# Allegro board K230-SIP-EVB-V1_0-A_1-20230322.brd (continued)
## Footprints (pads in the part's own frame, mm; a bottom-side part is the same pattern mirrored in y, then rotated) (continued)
TC1206
  rect 1.397x1.651 smd: 1(-1.397,0) 2(1.397,0)
TP40
  round 1.016 smd: 1(0,0)
TYPE-C-USB16-20-126-H-SMD-B
  round 0.711 hole 0.711 unplated: (-2.89,2.6) (2.89,2.6)
  rect 0.305x1.448 smd: A1(-3.375,3.974) A4(-2.6,3.974) A5(-1.25,3.974) A6(-0.25,3.974) A7(0.25,3.974) A8(1.25,3.974) A9(2.6,3.974) A12(3.375,3.974) B1(3.075,3.974) B4(2.3,3.974) B5(1.75,3.974) B6(0.75,3.974) B7(-0.75,3.974) B8(-1.75,3.974) B9(-2.3,3.974) B12(-3.075,3.974)
  oval 1.143x2.159 hole 0.762x1.778: P1(-4.32,3.13) P2(4.32,3.13)
  oval 1.143x1.651 hole 0.762x1.27: P3(-4.32,-1.05) P4(4.32,-1.05)
unnamed
  round 5.08 hole 2.921: (-14,14) (-14,-14) (14,14) (14,-14)
  round 1.524 hole 1.524 unplated: (-10.5,10.5) (-10.5,-10.5) (10.5,10.5) (10.5,-10.5)
WSON8-065-0303-008-N
  rect 0.635x0.381 smd: 1(-1.41,0.975) 2(-1.41,0.325) 3(-1.41,-0.325) 4(-1.41,-0.975) 5(1.41,-0.975) 6(1.41,-0.325) 7(1.41,0.325) 8(1.41,0.975)
  rect 1.651x2.54 smd: 9(0,0)
X2-3215-008
  rect 1.016x1.778 smd: 1(-1.257,0) 2(1.257,0)
X4-2520-010
  rect 1.016x0.889 smd: 1(-0.914,-0.762) 2(0.914,-0.762) 3(0.914,0.762) 4(-0.914,0.762)
X4-3225-009
  rect 1.27x1.143 smd: 1(-1.1,-0.8) 2(1.1,-0.8) 3(1.1,0.8) 4(-1.1,0.8)

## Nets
AVDD0V8_MIPI: C130.1 C131.1 C199.1 C200.1 C201.1 FB22.2 TP18.1(TP) U19.M4(AVDD0P8_MIPI_0) U19.N5(AVDD0P8_MIPI_1)
AVDD0V8_PLL: C148.1 C150.1 C197.1 C198.1 FB25.2 TP20.1(TP) U19.D8(AVDD0P8_PLL)
AVDD1V8_MIPI: C110.1 C111.1 C202.1 C203.1 C204.1 FB18.2 R90.1 TP15.1(TP) U19.L4(AVDD1P8_MIPI_1) U19.M6(AVDD1P8_MIPI_0)
GND: C1.2 C2.2 C3.2 C4.2 C5.2 C6.2 C7.2 C8.2 C9.2 C10.2 C11.2 C12.1 C13.2 C14.2 C15.2 C16.2 C17.2 C18.2 C19.2 C20.2 C21.2 C22.2 C23.2 C24.2 C25.2 C26.1 C28.2 C29.2 C30.1 C31.2 C32.2 C35.1 C36.2 C37.2 C40.2 C41.2 C42.2 C43.2 C44.2 C45.2 C46.2 C47.2 C48.2 C49.2 C50.2 C51.2 C52.2 C53.1 C55.2 C56.2 C57.1 C58.2 C59.2 C60.1 C61.1 C62.2 C63.2 C64.1 C66.2 C67.2 C68.1 C69.2 C70.2 C71.2 C72.1 C73.2 C74.2 C75.2 C76.2 C77.1 C79.2 C80.2 C81.1 C82.2 C83.2 C84.1 C85.2 C86.2 C87.1 C88.2 C90.2 C91.2 C92.1 C93.2 C94.2 C95.2 C96.1 C97.2 C98.2 C99.2 C100.2 C101.2 C102.2 C103.2 C104.2 C105.2 C106.2 C107.2 C108.2 C109.2 C110.2 C111.2 C112.2 C113.2 C114.2 C115.2 C116.2 C117.2 C118.2 C119.2 C120.2 C121.2 C122.2 C123.2 C124.2 C125.2 C126.2 C127.2 C128.2 C129.2 C130.2 C131.2 C132.2 C133.2 C134.2 C135.2 C136.2 C137.2 C138.2 C139.2 C140.2 C141.1 C142.2 C143.2 C144.2 C145.2 C146.2 C147.2 C148.2 C149.2 C150.2 C151.2 C152.2 C153.2 C154.2 C155.2 C156.2 C157.2 C158.2 C159.2 C160.2 C161.2 C162.2 C163.2 C164.2 C165.2 C166.2 C167.2 C168.2 C169.2 C170.2 C171.2 C172.2 C173.2 C174.2 C175.2 C176.2 C177.2 C178.2 C179.2 C180.2 C181.2 C182.2 C183.2 C184.2 C185.2 C186.2 C187.2 C188.2 C189.2 C190.2 C191.2 C192.2 C193.2 C194.2 C195.2 C196.2 C197.2 C198.2 C199.2 C200.2 C201.2 C202.2 C203.2 C204.2 C205.2 C206.2 C207.2 C208.2 C209.2 C210.2 C211.2 C212.2 C213.2 C214.2 C215.2 C216.2 C217.2 C218.2 C219.2 C220.2 C221.2 C222.2 C223.2 C224.2 C225.2 C226.2 C227.2 C228.2 C229.2 C230.2 C231.2 C232.2 C233.2 C234.2 C235.2 C236.2 C237.2 C238.1 C239.2 C240.2 C241.2 C242.2 C243.2 C244.2 C245.2 C246.2 C247.2 C248.2 C249.2 C250.2 C251.2 C253.1 C254.2 C255.1 C258.2 C259.1 C271.2 C272.2 C273.1 C274.1 C278.1 C280.1 C282.2 C283.1 C284.1 C286.1 C288.2 C289.1 C290.1 C291.2 C292.1 C293.2 C294.1 C295.2 C296.2 C297.2 C298.2 C299.2 C301.2 C302.2 C303.2 C304.2 C305.2 C306.2 C308.1 C310.1 C311.2 C312.2 D2.1(ANODE) J1.A1(GND0) J1.A12(GND1) J1.B1(GND3) J1.B12(GND2) J1.P1 J1.P2 J1.P3 J1.P4 J3.1 J3.2 J4.1 J4.2 J7.2 J7.9 J7.10 J11.A1(GND0) J11.A12(GND1) J11.B1(GND3) J11.B12(GND2) J11.P1 J11.P2 J11.P3 J11.P4 J18.2 J21.5 J21.6 J21.11 J21.12 J21.17 J21.18 J21.23 J21.24 J21.28 J21.29 J21.33 J21.37 J21.54 J21.55 J22.1 J22.2 J22.7 J22.12 J22.15 J22.18 J22.21 J22.24 J22.27 J22.30 J22.31 J22.32 J27.A1(GND0) J27.A12(GND1) J27.B1(GND3) J27.B12(GND2) J27.P1 J27.P2 J27.P3 J27.P4 J30.17 J30.18 J30.27 J30.28 J31.6 J31.12 J32.5 J33.3 K1.1 K2.3 K2.4 K3.3 LED2.2(ANODE) M1.1 M2.1 M3.1 M4.1 M5.1 M6.1 Q2.2(SOURCE) Q4.2(SOURCE) R1.2 R2.2 R6.2 R9.2 R16.2 R17.2 R19.2 R24.2 R31.2 R38.1 R44.2 R48.1 R52.1 R55.2 R59.2 R65.2 R69.2 R72.2 R78.2 R82.2 R87.2 R91.2 R93.2 R98.2 R103.2 R104.2 R138.1 R139.1 R140.1 R163.2 R164.2 R170.1 R171.1 R193.2 R208.2 R267.2 TP22.1(TP) TP23.1(TP) TP24.1(TP) TP25.1(TP) TP26.1(TP) TP27.1(TP) TP28.1(TP) TP29.1(TP) TP30.1(TP) TP31.1(TP) TP32.1(TP) TP33.1(TP) TP34.1(TP) TP35.1(TP) TP36.1(TP) TP37.1(TP) TP38.1(TP) TP39.1(TP) TP40.1(TP) TP41.1(TP) TP42.1(TP) TP43.1(TP) TP44.1(TP) TP45.1(TP) TVS1.2(A2) TVS2.1(A1) TVS3.1(A1) TVS4.2(A2) TVS5.2(A2) TVS6.2(A2) TVS7.2(A2) TVS8.2(A2) TVS9.2(A2) TVS10.2(A2) TVS11.2(A2) TVS12.2(A2) TVS13.2(A2) TVS14.2(A2) TVS15.2(A2) U1.2(GND) U2.3(GND) U2.7(POWERPAD) U3.1(AGND) U3.2(PGND) U4.3(GND2) U4.4(GND1) U4.5(AGND) U4.17(EPAD) U5.1(AGND) U5.2(PGND) U6.4(PGND1) U6.8(SGND) U6.9(PGND2) U7.4(PGND1) U7.8(SGND) U7.9(PGND2) U8.4(PGND1) U8.8(SGND) U8.9(PGND2) U9.4(PGND1) U9.8(SGND) U9.9(PGND2) U10.3(GND) U10.7(POWERPAD) U11.3(GND) U11.7(POWERPAD) U12.3(GND) U12.7(POWERPAD) U13.3(GND) U13.7(POWERPAD) U14.3(GND) U14.7(POWERPAD) U15.6(GND) U15.11(TP) U16.8(GND1) U16.9(GND2) U17.3(GND) U17.7(POWERPAD) U18.3(GND) U18.7(POWERPAD) U19.B16(VSS1) U19.C4(VSS2) U19.C5(VSS3) U19.C8(VSS4) U19.D6(VSS7) U19.D7(VSS8) U19.D9(AVSS0) U19.D13(VSS9) U19.E4(AVSS1) U19.E5(AVSS2) U19.E11(VSS11) U19.E12(VSS12) U19.E15(VSS13) U19.E16(VSS14) U19.F3(VSS15) U19.F8(VSS16) U19.F10(VSS17) U19.F12(VSS18) U19.G3(VSS20) U19.G4(VSS21) U19.G8(VSS22) U19.G10(VSS23) U19.G12(VSS24) U19.G13(VSS25) U19.G14(VSS26) U19.G15(VSS19) U19.G16(VSS72) U19.H3(VSS27) U19.H5(VSS28) U19.H7(VSS29) U19.H9(VSS30) U19.H13(VSS31) U19.H15(VSS32) U19.J4(VSS33) U19.J5(VSS34) U19.J7(VSS35) U19.J9(VSS36) U19.J12(VSS37) U19.J13(VSS38) U19.J14(VSS39) U19.J15(VSS40) U19.K5(VSS41) U19.K7(VSS42) U19.K9(VSS43) U19.K12(VSS44) U19.K13(VSS45) U19.K14(VSS46) U19.K15(VSS47) U19.K16(VSS48) U19.L3(VSS49) U19.L5(VSS50) U19.L7(VSS51) U19.L9(VSS52) U19.L12(VSS53) U19.L15(VSS54) U19.M3(VSS0) U19.M5(VSS55) U19.M7(VSS56) U19.M9(VSS57) U19.M11(VSS58) U19.M12(VSS59) U19.N4(VSS60) U19.N6(VSS61) U19.N7(VSS62) U19.N9(VSS63) U19.N12(VSS64) U19.P7(VSS66) U19.P8(VSS67) U19.P9(VSS68) U19.P14(VSS69) U19.R1(VSS70) U19.T13(VSS71) U20.7(GND) U21.7(GND) U23.6(VSS) U23.10(GND1) U23.11(GND2) U23.12(GND3) U23.13(GND4) U24.1(GND) U25.1(GND) U26.1(GND) U27.2(GND) U29.1(GND) U30.7(GND) U30.9(GND1) U31.7(GND) U31.9(GND1) U32.4(GND) U33.3(GND1) U33.11(GND0) U34.1(GND) U35.7(GND) U36.3(GND) U36.7(POWERPAD) U37.4(GND) U38.1(GND) U39.1(GND) U40.1(GND) U41.6(VSS) U41.10(GND1) U41.11(GND2) U41.12(GND3) U41.13(GND4) Y1.2(GND) Y2.2(GND#2) Y2.4(GND#4) Y4.2(GND)
VBUS: F1.1 J1.A4(VBUS0) J1.A9(VBUS1) J1.B4(VBUS3) J1.B9(VBUS2)
VBUS_CHARGE: C8.1 J2.1 LED1.1(CATHODE) U1.4(VIN)
VBUS_IN: C1.1 C2.1 C3.1 C4.1 C5.1 C6.1 C7.1 C288.1 D1.2(K) D2.2(CATHODE) D3.2(K) J2.2 U33.4(VDD5)
VDD0V8_CPU: C47.1 C48.1 C58.1 C59.1 C175.1 C176.1 C177.1 C178.1 C179.1 C299.1 FB6.2 FB7.2 TP4.1(TP) U19.E10(VDD0P8_CPU_0) U19.F9(VDD0P8_CPU_1) U19.G9(VDD0P8_CPU_2)
VDD0V8_DDR_CORE: C123.1 C124.1 C211.1 C212.1 C213.1 C214.1 C215.1 FB21.2 TP17.1(TP) U19.H10(VDD0P8_DDR_CORE_0) U19.J10(VDD0P8_DDR_CORE_1) U19.K10(VDD0P8_DDR_CORE_2) U19.L10(VDD0P8_DDR_CORE_3)
VDD0V8_KPU: C18.1 C21.1 C31.1 C32.1 C180.1 C181.1 C182.1 C183.1 C184.1 C185.1 C186.1 C187.1 C188.1 C189.1 FB2.1 FB3.1 TP1.1(TP) U19.F5(VDD0P8_KPU_0) U19.F6(VDD0P8_KPU_1) U19.F7(VDD0P8_KPU_2) U19.G5(VDD0P8_KPU_3) U19.G6(VDD0P8_KPU_4) U19.G7(VDD0P8_KPU_5)
VDD1V1_DDR: C135.1 C136.1 C143.1 C144.1 C221.1 C222.1 C223.1 C224.1 C225.1 C231.1 C232.1 C233.1 C234.1 FB23.2 FB24.2 R94.2 TP19.1(TP) U19.F11(VDD1P1_DDR_IO_0) U19.F15(VDD1P1_DDR_VDD2_0) U19.G11(VDD1P1_DDR_IO_1) U19.J11(VDD1P1_DDR_IO_2) U19.K11(VDD1P1_DDR_IO_3) U19.L11(VDD1P1_DDR_IO_4) U19.M15(VDD1P1_DDR_VDD2_1)
VDD1V1_DDR_DRAM: C156.1 C157.1 C218.1 C219.1 C220.1 C306.1 FB26.2 TP21.1(TP) U19.F16(VDD1P1_DDR_VDDQ_0) U19.L16(VDD1P1_DDR_VDDQ_1)
VDD1V8_DDR_VDD1: C98.1 C100.1 C116.1 C117.1 C226.1 C227.1 C228.1 FB16.2 FB19.2 TP13.1(TP) U19.H14(VDD1P8_DDR_VDD1)
VDD_0V8: C82.1 C83.1 C159.1 C160.1 C161.1 C162.1 C163.1 C164.1 C165.1 C166.1 C167.1 C168.1 C169.1 C170.1 C171.1 C172.1 C173.1 C174.1 FB11.2 TP8.1(TP) U19.E6(VDD0P8_CORE_1) U19.E7(VDD0P8_CORE_2) U19.E9(VDD0P8_CORE_3) U19.H6(VDD0P8_CORE_4) U19.H8(VDD0P8_CORE_5) U19.J6(VDD0P8_CORE_6) U19.J8(VDD0P8_CORE_7) U19.K6(VDD0P8_CORE_8) U19.K8(VDD0P8_CORE_9) U19.L6(VDD0P8_CORE_10) U19.L8(VDD0P8_CORE_11) U19.M8(VDD0P8_CORE_12) U19.M10(VDD0P8_CORE_13)
VDD_1V1: C300.1 R95.1
VDD_1V8: C88.1 C121.1 C133.1 C139.1 C140.1 C147.1 C190.1 C191.1 C192.1 C247.1 C248.1 C249.1 C250.1 C251.1 C253.2 C254.1 C258.1 C291.1 C303.1 C304.1 FB12.2 J7.1 Q3.1(GATE) R47.1 R63.2 R73.2 R80.2 R89.1 R96.2 R99.2 R101.2 R122.1 R123.1 R124.1 R125.1 R126.1 R132.1 R136.1 R168.1 R179.1 R180.1 R181.1 R182.1 R183.1 R184.1 R185.1 R186.1 R195.1 R212.1 R222.1 TP9.1(TP) U13.6(IN) U15.1(IN1) U15.2(IN2) U16.4(IN) U17.6(IN) U19.D10(VDD1P8_1) U19.E8(VDD1P8_0) U19.F4(VDDIO3P3_3) U19.H4(VDDIO3P3_1) U19.K4(VDDIO3P3_4) U19.N10(VDDIO3P3_0) U19.N11(VDDIO3P3_5) U20.2(VCCA) U21.2(VCCA) U35.2(VCCA) U37.8(VCC) Y1.4(VCC)
VDD_1V8_ADC: C97.1 C193.1 C194.1 FB15.2 TP12.1(TP) U19.D5(AVDD1P8_ADC)
VDD_1V8_CODEC: C95.1 C195.1 C196.1 FB14.2 TP11.1(TP) U19.D4(AVDD1P8_CODEC)
VDD_1V8_USB: C94.1 C209.1 C210.1 FB13.2 TP10.1(TP) U19.C6(AVDD1P8_USB)
VDD_3V3: C73.1 C74.1 C99.1 C104.1 C112.1 C153.1 C205.1 C206.1 C271.1 C272.1 C311.1 C312.1 FB9.2 FB33.1 J21.57 J21.59 J22.5 J22.6 R37.1 R50.2 R53.2 R57.2 R84.2 R155.1 R194.2 R204.2 R220.1 R223.1 R224.2 R226.2 R265.1 R273.1 R274.1 R275.1 R276.1 R277.1 R278.1 R279.1 TP6.1(TP) TVS5.1(A1) TVS14.1(A1) U10.6(IN) U11.6(IN) U12.6(IN) U18.6(IN) U19.C9(VDD3P3_SD) U23.4(VDD) U41.4(VDD)
VDD_3V3_K210: FB10.2 J30.29 J30.30
VDD_3V3_USB: C70.1 C71.1 C207.1 C208.1 FB8.2 TP5.1(TP) U19.C7(AVDD3P3_USB)
VDD_5V: C9.1 C10.1 C11.1 C15.1 C16.1 C17.1 C24.1 C25.1 C26.2 C44.1 C45.1 C46.1 C51.1 C52.1 C53.2 C62.1 C63.1 C64.2 C75.1 C76.1 C77.2 C85.1 C86.1 C87.2 C137.1 C145.1 C273.2 C283.2 C284.2 C302.1 J2.3 J3.3 J3.4 J4.3 J4.4 J32.6 J33.1 Q5.2(SOURCE) R3.1 R5.1 R8.2 R14.1 R15.1 R23.2 R28.2 R30.1 R35.2 R42.1 R43.2 R49.2 R137.1 R162.1 R207.1 R264.1 R266.2 TP3.1(TP) U1.3(BAT) U2.6(IN) U3.3(VIN) U4.1(VIN3) U4.2(VIN1) U4.16(VIN2) U5.3(VIN) U6.3(IN) U7.3(IN) U8.3(IN) U9.3(IN) U15.4(BIAS) U16.1(BIAS) U27.5(IN) U30.6(VDD) U31.6(VDD) U36.6(IN)
VDD_5V_O: J21.56 J21.58 J21.60 J22.3 J22.4 Q5.3(DRAIN) R264.2
3D_CTRL_IN: J21.49 U19.P15(GPIO10)
3D_CTRL_OUT1: J21.47 U19.P16(GPIO11)
3D_CTRL_OUT2: J21.46 U19.P13(GPIO12)
ADC0: R229.1 U19.A7(ADC_0)
ADC1: R230.1 U19.A6(ADC_1)
ADC2: R178.2 U19.B6(ADC_2)
BOOT_CTL0: R99.1 SW1.1(A1) TVS3.2(A2) U19.C14(GPIO0)
BOOT_CTL1: R101.1 SW1.2(A2) TVS2.2(A2) U19.C15(GPIO1)
CC1: J1.A5(CC1) J1.B5(CC2) R1.1
CC_T: J27.A5(CC1) J27.B5(CC2) R193.1 TVS7.1(A1)
CLK24M_XIN: R97.2 R100.2 U19.A15(CLK24M_XIN)
CLK24M_XOUT: R105.2 U19.B15(CLK24M_XOUT)
CTRL0: J36.1 R170.2 U30.1(CTRL)
CTRL1: J36.2 R171.2 U31.1(CTRL)
DDR_VREF: C240.1 C241.1 C300.2 R95.2 R98.1 U19.H11(DDR_VREF)
DEBUG_DM: J27.A7(DN1) J27.B7(DN2) R188.1 U34.2(I/O_1)
DEBUG_DP: J27.A6(DP1) J27.B6(DP2) R187.1 U34.3(I/O_2)
EN: C115.1 C118.1 R57.1 R60.1 U12.4(EN)
EN_CORE_K210: J35.2 R64.1
EN_DDR_K210: J35.1 R86.1 R231.1
GPIO7: J34.3 U19.M16(GPIO7)
GPIO8: J34.8 U19.N16(GPIO8)
GPIO20: R213.1 U19.H2(GPIO20)
GPIO21: R214.1 U19.H1(GPIO21)
GPIO22: R215.1 U19.J1(GPIO22)
GPIO23: R216.1 U19.J2(GPIO23)
GPIO24: Q3.2(SOURCE) R222.2 U19.J3(GPIO24) U21.6(A4)
GPIO24_3V3: Q1.1(GATE) Q3.3(DRAIN) R135.2 R223.2
GPIO25: R127.1 R176.2
GPIO32: J38.1 R115.2 U21.12(B1)
GPIO32_1V8: R133.1 R177.2
GPIO33: J38.2 R116.2 U21.11(B2)
GPIO33_1V8: R134.1 R174.2
GPIO34: J34.1 J37.2 R118.2 U20.12(B1)
GPIO34_1V8: J21.32 R128.1
GPIO35: J32.1 J37.1 R119.2 U20.11(B2)
GPIO35_1V8: J21.34 R129.1
GPIO36: J37.3 R120.2 U20.10(B3)
GPIO36_1V8: J21.36 R130.1
GPIO37: J38.3 R121.2 U20.9(B4)
GPIO37_1V8: R131.1 R175.2
GPIO38: J34.9 U19.E3(GPIO38)
GPIO39: J34.14 U19.D1(GPIO39)
GPIO40: R110.1 U19.D2(GPIO40)
GPIO41: R111.1 U19.C1(GPIO41)
GPIO44: R112.1 U19.B1(GPIO44)
GPIO45: R113.1 U19.C2(GPIO45)
GPIO48: R218.1 U19.D3(GPIO48)
GPIO49: R219.1 U19.C3(GPIO49)
GPIO59: R173.2 U19.P4(GPIO59)
GPIO60: R114.1 U19.N3(GPIO60)
GPIO61: R117.1 U19.P3(GPIO61)
HP_INSERT_DET: J34.12 R169.1
HPOUTL: C281.1 C309.1 U19.B2(LINEOUTN)
HPOUTR: C279.1 C307.1 U19.A2(LINEOUTP(L))
HSYNC0: J21.51 J34.11 R229.2
IIC0_SCL: J21.38 R114.2 R179.2
IIC0_SDA: J21.40 R117.2 R180.2
IIC1_SCL: J21.43 R110.2 R181.2 R269.1
IIC1_SDA: J21.45 R111.2 R182.2 R268.1
IIC3_SCL: J21.41 R112.2 R183.2
IIC3_SDA: J21.39 R113.2 R184.2
IIC4_SCL: J22.8 J34.4 R185.2 R271.1
IIC4_SDA: J22.9 J34.6 R186.2 R270.1
INA226_0V8+: C78.2 C79.1 C80.1 C81.2 J30.2 L6.2 R40.1 R41.2
INA226_0V8-: FB11.1 J30.4 R40.2
INA226_1V8IO+: C89.2 C90.1 C91.1 C92.2 C93.1 J30.6 L7.2 R45.1 R46.2
INA226_1V8IO-: FB12.1 FB13.1 FB14.1 FB15.1 J30.8 R45.2
INA226_AVDDMIPI+: C128.1 C129.1 J30.9 R66.1 R68.1 U14.1(OUT)
INA226_AVDDMIPI-: FB22.1 J30.11 R66.2
INA226_CORE0+: C54.2 C55.1 C56.1 C57.2 L4.2 R25.1 R27.1 R29.2
INA226_CORE0-: FB7.1 R26.1 R27.2
INA226_CORE+: C42.1 C43.1 C49.1 J30.13 L3.2 R22.1 R25.2 U5.8(VOS)
INA226_CORE-: FB6.1 J30.15 R22.2 R26.2
INA226_DDR_CORE+: C122.1 C125.1 J30.23 R61.1 R62.1 U13.1(OUT)
INA226_DDR_CORE-: FB21.1 J30.25 R61.2
INA226_DDR_DRAM+: C154.1 C155.1 J30.10 R83.1 R85.1 U18.1(OUT)
INA226_DDR_DRAM-: FB26.1 J30.12 R83.2
INA226_DDR_IO0+: C141.2 C142.1 R74.1 R76.1 R77.1 U16.5(OUT1) U16.6(OUT2)
INA226_DDR_IO0-: FB24.1 R75.1 R76.2
INA226_DDR_IO+: C134.1 J30.14 R70.1 R71.1 R74.2 U15.9(OUT1) U15.10(OUT2)
INA226_DDR_IO-: FB23.1 J30.16 R70.2 R75.2
INA226_KPU0+: C28.1 C29.1 C30.2 L2.2 R10.1 R12.1 R13.1
INA226_KPU0-: FB3.2 R11.1 R12.2
INA226_KPU+: C19.1 C20.1 C22.1 J30.5 L1.2 R7.1 R10.2 U3.8(VOS)
INA226_KPU-: FB2.2 J30.7 R7.2 R11.2
INA226_MIPI1V8+: C113.1 C114.1 J30.20 R56.1 R58.1 U12.1(OUT)
INA226_MIPI1V8-: FB18.1 FB19.1 FB20.1 J30.22 R56.2
INA226_PLL+: C149.1 C151.1 J30.1 R79.1 R81.1 U17.1(OUT)
INA226_PLL-: FB25.1 J30.3 R79.2
INA226_USB+: C65.2 C66.1 C67.1 C68.2 C69.1 FB10.1 J30.19 L5.2 R34.1 R36.2
INA226_USB-: FB8.1 FB9.1 J30.21 R34.2
JTAG_RST: J7.7 R123.2 U19.N13(GPIO6)
JTAG_TCK: J7.3 R126.2 U19.L14(GPIO2)
JTAG_TDI: J7.5 R125.2 U19.N15(GPIO3)
JTAG_TDO: J7.4 U19.N14(GPIO4)
JTAG_TMS: J7.6 R124.2 U19.M14(GPIO5)
K230_RSTN: C238.2 K1.2 R89.2 R90.2 R92.2 TVS1.1(A1) U19.C12(RSTN)
LMICN: C275.1 U19.A5(MICIN1N)
LMICP: C277.1 U19.B5(MICIN1P(L))
M_CLK1: J21.26 U19.P12(GPIO13)
M_CLK2: J21.31 U19.L13(GPIO62)
M_CLK3: J21.35 U19.M13(GPIO63)
MICBIAS: C237.1 C239.1 C286.2 R165.1 R172.2 U19.A4(MIC_BIAS)
MIPI_CSI0_CLK0_N: J21.1 U19.P1(MIPI_RX0_CLK_N)
MIPI_CSI0_CLK0_P: J21.3 U19.P2(MIPI_RX0_CLK_P)
MIPI_CSI0_CLK1_N: J21.14 U19.R4(MIPI_RX1_CLK_N)
MIPI_CSI0_CLK1_P: J21.16 U19.T4(MIPI_RX1_CLK_P)
MIPI_CSI0_CLK2_N: J21.25 U19.K1(MIPI_RX2_CLK_N)
MIPI_CSI0_CLK2_P: J21.27 U19.K2(MIPI_RX2_CLK_P)
MIPI_CSI0_D0_N: J21.4 U19.R2(MIPI_RX0_D0_N)
MIPI_CSI0_D0_P: J21.2 U19.T2(MIPI_RX0_D0_P)
MIPI_CSI0_D1_N: J21.9 U19.N1(MIPI_RX0_D1_N)
MIPI_CSI0_D1_P: J21.7 U19.N2(MIPI_RX0_D1_P)
MIPI_CSI0_D2_N: J21.10 U19.T3(MIPI_RX1_D2_N)
MIPI_CSI0_D2_P: J21.8 U19.R3(MIPI_RX1_D2_P)
MIPI_CSI0_D3_N: J21.20 U19.R5(MIPI_RX1_D3_N)
MIPI_CSI0_D3_P: J21.22 U19.T5(MIPI_RX1_D3_P)
MIPI_CSI0_D4_N: J21.21 U19.L2(MIPI_RX2_D4_N)
MIPI_CSI0_D4_P: J21.19 U19.L1(MIPI_RX2_D4_P)
MIPI_CSI0_D5_N: J21.13 U19.M2(MIPI_RX2_D5_N)
MIPI_CSI0_D5_P: J21.15 U19.M1(MIPI_RX2_D5_P)
MIPI_DSI_CLK0_N: J22.19 U19.R9(MIPI_TX0_CLK_N)
MIPI_DSI_CLK0_P: J22.20 U19.T9(MIPI_TX0_CLK_P)
MIPI_DSI_D0_N: J22.22 U19.R8(MIPI_TX0_D0_N)
MIPI_DSI_D0_P: J22.23 U19.T8(MIPI_TX0_D0_P)
MIPI_DSI_D1_N: J22.16 U19.R10(MIPI_TX0_D1_N)
MIPI_DSI_D1_P: J22.17 U19.T10(MIPI_TX0_D1_P)
MIPI_DSI_D2_N: J22.13 U19.T7(MIPI_TX1_D2_N)
MIPI_DSI_D2_P: J22.14 U19.R7(MIPI_TX1_D2_P)
MIPI_DSI_D3_N: J22.25 U19.R6(MIPI_TX1_D3_N)
MIPI_DSI_D3_P: J22.26 U19.T6(MIPI_TX1_D3_P)
MIPI_DSI_D_RST: J22.28 R214.2
MIPI_DSI_LCD_EN: J22.29 R213.2
MIPI_DSI_T_INT: J22.10 R215.2
MIPI_DSI_T_RST: J22.11 R216.2
NVCC_SD: C301.1 C305.1 FB33.2 R156.1 R157.1 R158.1 R159.1 R160.1 R161.1 R209.1 R210.1 R225.2 R227.2 TP16.1(TP) U19.N8(VDDIO3P3_2) U36.1(OUT)
PG_0V8: C72.2 C96.2 R35.1 R42.2 R49.1 U7.7(EN) U8.2(PG) U9.7(EN)
PG_1V8: C152.1 R47.2 R80.1 U9.2(PG) U15.5(EN) U16.2(EN) U17.4(EN)
PG_3V3: C103.1 R37.2 R50.1 R60.2 R211.1 U7.2(PG) U10.4(EN)
PW_EN: C23.1 C35.2 C50.1 C60.2 C84.2 C132.1 J31.14 J31.16 R8.1 R14.2 R17.1 R23.1 R28.1 R43.1 R67.1 U3.4(EN) U4.15(EN) U5.4(EN) U6.7(EN) U8.7(EN) U14.4(EN)
QSPI0_CLK: U19.E1(GPIO15) U37.6(CLK)
QSPI0_CS0: R212.2 U19.E2(GPIO14) U37.1(C\S\)
QSPI0_D0: U19.F2(GPIO16) U37.5(DI(IO0))
QSPI0_D1: U19.F1(GPIO17) U37.2(DO(IO1))
QSPI0_D2: U19.G1(GPIO18) U37.3(W\P\(IO2))
QSPI0_D3: U19.G2(GPIO19) U37.7(H\O\L\D\(IO3))
RMICN: C285.1 U19.B3(CODEC_MICNR)
RMICP: C287.1 U19.A3(CODEC_MICPR)
RTC_1V8: C13.1 C14.1 C229.1 C230.1 C244.1 FB1.2 J31.4 J31.8 J31.10 K2.2 R202.2 R203.2 TP2.1(TP) U19.D11(AVDD1P8_LDO) U19.D12(AVDD1P8_RTC) Y4.4(VCC)
RTC_CLK_IN: R107.2 R108.2 U19.D15(CLK32K768_XIN)
RTC_CLK_OUT: R106.1 U19.D16(CLK32K768_XOUT)
RTC_INT0: R196.1 TVS8.1(A1) U19.C16(INT0)
RTC_INT1: R198.1 TVS9.1(A1) U19.D14(INT1)
RTC_INT2: J32.4 R197.1 TVS10.1(A1) U19.E14(INT2)
RTC_INT4: J33.2 R199.1 TVS11.1(A1) U19.F14(INT4)
RTC_OUT0: R200.1 R202.1 TVS12.1(A1) U19.F13(OUT0)
RTC_OUT1: R92.1 U19.E13(OUT1)
SD2_CLK: R156.2 U19.P11(GPIO26) U23.5(CLK) U24.3(I/O_2)
SD2_CMD: R157.2 U19.P10(GPIO27) U23.3(CMD) U24.2(I/O_1)
SD2_DATA0: R161.2 U19.R16(GPIO28) U23.7(DAT0) U26.2(I/O_1)
SD2_DATA1: R160.2 U19.R15(GPIO29) U23.8(DAT1) U26.3(I/O_2)
SD2_DATA2: R159.2 U19.R14(GPIO30) U23.1(DAT2) U25.2(I/O_1)
SD2_DATA3: R158.2 U19.R13(GPIO31) U23.2(CD/DAT3) U25.3(I/O_2)
SD2_DET: J34.2 R155.2 TVS4.1(A1) U23.9(DET)
SDIO_CLK: R274.2 U19.B14(MMC0_CLK) U38.3(I/O_2) U41.5(CLK)
SDIO_CMD: R273.2 U19.A14(MMC0_CMD) U38.2(I/O_1) U41.3(CMD)
SDIO_DAT0: R278.2 U19.A12(MMC0_D0) U40.2(I/O_1) U41.7(DAT0)
SDIO_DAT1: R276.2 U19.A10(MMC0_D1) U40.3(I/O_2) U41.8(DAT1)
SDIO_DAT2: R277.2 U19.A11(MMC0_D2) U39.2(I/O_1) U41.1(DAT2)
SDIO_DAT3: R275.2 U19.A13(MMC0_D3) U39.3(I/O_2) U41.2(CD/DAT3)
SDIO_DET: J34.15 R279.2 TVS15.1(A1) U41.9(DET)
SYS_ON_OFF: C293.1 J31.2 K2.1
SYS_SW: C294.2 K3.2 R201.1 TVS13.1(A1)
UART0_RXD: J34.16 U35.4(A2)
UART0_RXD_3V3: J28.1 R189.2 U35.11(B2)
UART0_TXD: J34.10 U35.3(A1)
UART0_TXD_3V3: J28.2 R190.2 U35.12(B1)
UART4_RXD: R219.2 U35.6(A4)
UART4_RXD_3V3: J32.2 R191.2 U35.9(B4)
UART4_TXD: R218.2 U35.5(A3)
UART4_TXD_3V3: J32.3 R192.2 U35.10(B3)
USB0_OTG_DN: J11.A7(DN1) J11.B7(DN2) U19.A8(USB0_DN) U29.2(I/O_1)
USB0_OTG_DP: J11.A6(DP1) J11.B6(DP2) U19.B8(USB0_DP) U29.3(I/O_2)
USB0_OTG_ID: J11.A5(CC1) J11.B5(CC2) R221.1 TVS6.1(A1) U19.A9(USB0_ID)
USB0_OTG_VBUS: D4.2(K) J11.A4(VBUS0) J11.A9(VBUS1) J11.B4(VBUS3) J11.B9(VBUS2) R272.2 U29.4(VCC)
VAA_DDR: C107.1 C108.1 C119.1 C120.1 C216.1 C217.1 FB17.2 FB20.2 TP14.1(TP) U19.H12(VAA_DDR)
VCM: C235.1 C236.1 U19.B4(CODEC_VCM)
VPWM_CORE: J34.7 R33.2
VPWM_KPU: J34.5 R21.2
VSYNC0: J21.53 J34.13 R230.2
N22175184: D1.1(A) F1.2
N22177941: R9.1 U3.9(VSET/VID/PG)
N22177946: L1.1 U3.7(SW)
N22182672: C41.1 R20.2 R21.1
N22185023: LED1.2(ANODE) U1.1(\\C\H\A\G\)
N22185059: R2.1 U1.5(PROG)
N22185516: C101.1 C102.1 FB16.1 R51.1 U10.1(OUT)
N22185553: R51.2 R52.2 U10.2(FB)
N22186056: C105.1 C106.1 FB17.1 R54.1 U11.1(OUT)
N22186079: C109.1 R53.1 R231.2 U11.4(EN)
N22186091: R54.2 R55.1 U11.2(FB)
N22187793: R58.2 R59.1 U12.2(FB)
N22191614: C126.1 R63.1 R64.2 U13.4(EN)
N22191677: R62.2 R65.1 U13.2(FB)
N22192931: C127.1 R67.2 R207.2 U14.6(IN)
N22192964: R68.2 R69.1 U14.2(FB)
N22212532: R13.2 R16.1 R20.1 U4.6(VSENSE)
N22217230: R24.1 U5.9(VSET/VID/PG)
N22217278: L3.1 U5.7(SW)
N22249226: R81.2 R82.1 U17.2(FB)
N22250085: C146.1 U16.3(SS)
N22250107: R77.2 R78.1 U16.7(FB)
N22277860: C274.2 D4.1(A) R272.1 U27.1(OUT)
N22292047: J7.8 R122.2
N22293444: R91.1 U19.C13(TEST_EN)
N22293459: R104.1 SW1.4(B2)
N22293460: R103.1 SW1.3(B1)
N22293491: R97.1 Y1.3(OUT)
N22293492: R96.1 Y1.1(EN)
N22305390: R121.1 U19.T11(GPIO37)
N22305392: R120.1 U19.T12(GPIO36)
N22305394: R119.1 U19.T14(GPIO35)
N22305396: R118.1 U19.T15(GPIO34)
N22305398: R116.1 U19.R11(GPIO33)
N22325333: R138.2 U19.B9(USB0_TXRTUNE)
N22325479: R137.2 U19.B7(USB0_VBUS)
N22328655: FB29.1 U30.8(VON)
N22328657: FB30.1 U30.5(VOP)
N22328764: C282.1 J18.6 R168.2 R169.2
N22328820: C276.2 C277.2 J18.1 R165.2
N22328860: C275.2 C276.1 R164.1
N22328921: C279.2 J18.4
N22328923: C281.2 J18.3
N22328925: J18.8 R166.2
N22328935: J18.7 R167.2
N22328937: C280.2 R167.1
N22328939: C278.2 R166.1
N22328989: FB31.1 U31.8(VON)
N22328991: FB32.1 U31.5(VOP)
N22333182: R140.2 U19.P6(MIPI_REXT)
N22333186: R139.2 U19.P5(MIPI_ATB)
N22367376: R115.1 U19.R12(GPIO32)
N22368053: R172.1 U32.1(VDD)
N22368198: C287.2 U32.3(OUTPUT+)
N22368201: C285.2 U32.2(OUTPUT-)
N22445143: C54.1 R29.1 R31.1 R32.1 U6.1(FB)
N22445145: C61.2 R32.2 R33.1
N22445207: R30.2 U6.2(PG)
N22445414: L4.1 U6.6(LX)
N22458660: C78.1 R41.1 R44.1 U8.1(FB)
N22458931: L6.1 U8.6(LX)
N22477210: C89.1 R46.1 R48.2 U9.1(FB)
N22477358: L7.1 U9.6(LX)
N22506626: D3.1(A) J27.A4(VBUS0) J27.A9(VBUS1) J27.B4(VBUS3) J27.B9(VBUS2)
N22537740: C27.2 L2.1 U4.10(PH3) U4.11(PH1) U4.12(PH2)
N22537802: C27.1 U4.13(BOOT)
N22537853: R15.2 U4.14(PWRGD)
N22538184: R19.1 U4.8(RT)
N22538189: C36.1 R18.1 U4.7(COMP)
N22538194: C37.1 U4.9(SS/TR)
N22561506: C65.1 R36.1 R38.2 U7.1(FB)
N22561654: L5.1 U7.6(LX)
N22646851: J21.52 R178.1
N22647187: J21.42 R174.1
N22647219: J21.44 R175.1
N22647230: J21.48 R176.1
N22647232: J21.50 R177.1
N22647453: J21.30 R173.1
N22675755: C158.1 R84.1 R86.2 U18.4(EN)
N22675895: R85.2 R87.1 U18.2(FB)
N22676270: C138.1 U15.7(SS)
N22676291: R73.1 U15.3(PG)
N22676313: R71.2 R72.1 U15.8(FB)
N22682206: C40.1 R18.2
N22702416: C255.2 R224.1 R225.1 U20.1(VCCB)
N22702442: R132.2 U20.8(OE)
N22756394: R187.2 U33.1(UD+)
N22756396: R188.2 U33.2(UD-)
N22756731: R189.1 U33.8(TXD0)
N22756757: R190.1 U33.9(RXD0)
N22756876: R191.1 U33.5(TXD1)
N22756879: R192.1 U33.6(RXD1)
N22757084: C289.2 U33.10(V3)
N22757146: C290.2 R194.1 U33.7(VIO)
N22778016: C243.1 R102.2 R105.1 Y2.3(IN)
N22778033: C242.1 R100.1 R102.1 Y2.1(OUT)
N22813541: R108.1 Y4.3(OUT)
N22813555: C245.1 R106.2 R109.1 Y3.1
N22813557: C246.1 R107.1 R109.2 Y3.2
N22833174: C259.2 R226.1 R227.1 U21.1(VCCB)
N22833184: R136.2 U21.8(OE)
N22838956: R135.1 U21.9(B4)
N22845324: C292.2 R204.1 U35.1(VCCB)
N22845340: R195.2 U35.8(OE)
N22848145: C12.2 FB1.1 R4.2 U2.1(OUT)
N22848155: R5.2 U2.4(EN)
N22848169: R4.1 R6.1 U2.2(FB)
N22850140: J31.3 R198.2
N22850142: J31.1 R196.2
N22850146: J31.5 R197.2
N22850259: J31.15 R201.2
N22850264: J31.13 R200.2
N22850508: K3.1 R203.1
N22859730: R94.1 U19.J16(DDR_ZQ)
N22859732: R93.1 U19.H16(DDR_ZN)
N22896944: R133.2 U21.3(A1)
N22896964: R134.2 U21.4(A2)
N22896985: R131.2 U20.6(A4)
N22897005: R130.2 U20.5(A3)
N22897025: R129.2 U20.4(A2)
N22897045: R128.2 U20.3(A1)
N22994425: J31.9 R199.2
N23005611: C296.1 FB29.2 J19.1
N23005650: C295.1 FB30.2 J19.2
N23005853: C297.1 FB31.2 J20.1
N23005873: C298.1 FB32.2 J20.2
N23088396: Q1.2(SOURCE) R208.1 R209.2 U36.2(FB)
N23088453: Q1.3(DRAIN) R210.2
N23088513: R211.2 U36.4(EN)
N23103726: Q2.3(DRAIN) R162.2 U27.4(EN)
N23103803: Q2.1(GATE) R220.2 R221.2
N23147657: Q4.1(GATE) R265.2 R267.1
N23147659: Q4.3(DRAIN) R263.1 R266.1
N23147737: Q5.1(GATE) R263.2
N23166270: R268.2 U3.5(SDA)
N23166302: R269.2 U3.6(SCL)
N23166482: R270.2 U5.5(SDA)
N23166503: R271.2 U5.6(SCL)
N23178807: C307.2 U30.4(INP)
N23178824: C308.2 U30.3(INN)
N23178875: C309.2 U31.4(INP)
N23178892: C310.2 U31.3(INN)
N222777460: R163.1 U27.3(ISET)
N228657051: LED2.1(CATHODE) R3.2
N228906461: R127.2 U19.K3(GPIO25)

Pads without a net: ID1 1; ID2 1; ID3 1; ID4 1; ID5 1; ID6 1; J1 A6 A7 A8 B6 B7 B8; J11 A8 B8; J27 A8 B8; J30 24 26; J31 7 11; U2 5; U6 5; U7 5; U8 5; U9 5; U10 5; U11 5; U12 5; U13 5; U14 5; U17 5; U18 5; U19 A1 A16 B10 B11 B12 B13 C10 C11 T1 T16; U21 5 10; U24 4; U25 4; U26 4; U30 2; U31 2; U34 4; U36 5; U38 4; U39 4; U40 4; Y4 1

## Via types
v1: diameter 0.559, hole 0.254, TOP to BOTTOM, 1117 vias
v2: diameter 0.457, hole 0.203, TOP to BOTTOM, 67 vias
v3: diameter 0.356, hole 0.203, TOP to BOTTOM, 157 vias

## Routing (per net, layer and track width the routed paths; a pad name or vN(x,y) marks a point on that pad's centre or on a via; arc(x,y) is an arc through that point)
AVDD0V8_MIPI: length 6.5
  TOP w0.254: v3(28.64,83.26) U19.M4 U19.N5
  BOTTOM w0.305: v3(28.64,83.26) 28.64,84.64 C200.1 C201.1 27.18,84.84 27.01,84.67 26.58,84.67 26.16,85.09 C199.1
  vias: v1(7.87,40.26) v1(7.87,39.24) v1(9.14,40.26) v1(9.14,39.24)
AVDD0V8_PLL: length 27.2
  TOP w0.254: U19.D8 v3(34.49,80.01)
  TOP w0.381: TP20.1 51.05,68.45 v1(51.24,68.26)
  BOTTOM w0.254: v3(34.49,80.01) 35.05,80.01 35.43,80.39 C198.1 35.94,80.14 36.2,79.88 38.23,79.88
  BOTTOM w0.381: 38.23,79.88 38.61,79.88 C197.1 39.62,78.49 40.01,78.11 44.58,78.11 46.86,75.82 46.86,72.64 v1(51.24,68.26) 52.32,67.18
AVDD1V8_MIPI: length 71.7
  TOP w0.254: U19.L4 v3(29.29,82.61) ; U19.M6 v3(28.64,81.96)
  TOP w0.381: v1(73.03,45.21) 69.35,41.54 43.32,41.54 42.61,40.83 v1(39.62,40.83)
  ART03 w0.381: v1(27.94,58.8) 29.34,57.4 39.5,57.4 40.89,56.01 40.89,53.21 39.88,52.2 39.88,47.12 39.62,46.86 v1(39.62,40.83)
  BOTTOM w0.381: v1(73.03,45.21) 73.03,48.13 R90.1
  vias: v1(25.65,63.12) v1(25.65,62.1) v1(26.92,63.12) v1(26.92,62.1)
GND: length 341.6
  TOP w0.203: U35.7 46.79,109.42 v1(46.48,109.73) ; v1(46.61,116.71) 46.92,116.41 U21.7 ; U20.7 37.39,116.41 v1(37.08,116.71)
  TOP w0.254: U19.H15 v3(31.89,75.46) ; v3(31.89,75.46) U19.G16 ; v3(31.89,75.46) U19.G15 ; U19.G13 U19.G14 v3(31.89,76.11) ; U19.D13 v3(34.49,76.76) ; U19.N9 v3(28.64,79.36) U19.M9 ; U19.G12 U19.F12 v3(33.19,77.41) U19.E12 ; U19.J5 v3(31.24,82.61) U19.H5 ; U19.J7 v3(31.24,81.31) U19.H7 ; U19.R1 v3(26.69,85.21) ; U19.E5 v3(33.84,82.61) U19.E4 ; U19.E15 v3(33.84,75.46) U19.E16 ; U19.K13 v3(29.94,76.76) U19.K14 ; U19.D9 v3(33.84,79.36) ; v1(58.29,26.29) 58.03,26.55 U4.5 ; U19.M3 v3(29.29,83.91) U19.L3 ; U19.J13 v3(31.24,76.76) U19.H13 ; U19.K9 v3(29.94,80.01) U19.L9 ; U19.N4 v3(27.99,83.26) ; U19.T13 v3(25.91,77.09) ; U19.C8 v3(34.49,80.66) ; U19.F3 v3(32.54,83.26) ; v3(32.54,83.26) U19.G4 ; v3(32.54,83.26) U19.G3 ; U19.P8 v3(27.34,80.66) U19.P7 ; U19.K16 v3(29.94,74.81) ; U19.L5 v3(29.94,82.61) U19.K5 ; U19.L7 v3(29.94,81.31) U19.K7 ; U19.B16 v3(35.79,74.81) ; U19.J12 v3(30.59,77.41) U19.K12 ; U19.J9 v3(31.24,80.01) U19.H9 ; U19.J15 v3(30.59,76.11) U19.J14 ; U19.G8 v3(32.54,80.66) U19.F8 ; U19.H3 v3(31.24,83.26) U19.J4 ; U19.M11 v3(28.64,78.71) ; U19.P14 v3(27.34,76.11) ; U19.M7 v3(28.64,80.66) U19.N7 ; U19.C5 v3(35.14,82.61) U19.C4 ; U19.D6 v3(34.49,81.31) U19.D7 ; U19.L12 U19.M12 v3(28.64,78.06) U19.N12 ; U19.G10 v3(32.54,78.71) U19.F10 ; U19.P9 v3(27.99,79.36) ; U19.N6 v3(28.64,81.31) ; U4.4 56.63,25.13 v1(56.39,24.89) 56.13,25.15 U4.3 ; U19.M5 v3(29.29,81.96) ; U19.K15 v3(29.94,76.11) U19.L15 ; U19.E11 v3(33.19,78.06)
  TOP w0.305: J21.5 v1(33.75,131.6) ; J22.24 v1(8.99,100.41) ; J21.12 35.25,132.92 34.8,132.46 v1(34.42,132.46) 34.16,132.46 33.75,132.87 J21.6 ; R38.1 v1(24,17.14) ; R44.2 v1(10.92,50.93) ; J21.11 v1(35.25,128.91) ; U12.3 29.83,47.95 ; C60.1 v1(40.39,31.62) ; J21.28 39.25,134.86 v1(38.73,135.38) 38.25,134.9 J21.24 ; U6.8 44.97,30.22 ; U7.8 23.25,21.47 ; U8.8 15.38,51.68 ; J22.15 v1(8.76,95.91) ; J21.17 v1(36.75,128.91) ; v1(8.89,92.33) 8.47,91.91 J22.7 ; J21.23 38.27,130.24 v1(38.27,128.91) ; J22.12 v1(8.89,94.41) ; J21.54 v1(45.76,132.59) ; U9.8 64.65,67.69 ; U15.6 38.46,49.77 v1(38.61,49.91) ; R31.2 v1(40.39,29.46) ; J22.1 8.65,88.91 v1(8.89,89.15) 8.63,89.41 J22.2 ; v1(46.35,128.91) 46.26,129 J21.55 ; J22.27 v1(8.99,101.91) ; v1(40.01,128.78) 39.75,129.03 J21.29 ; J22.21 v1(8.76,98.91) ; 61.09,66.93 60.45,66.93 v1(60.2,66.67) ; J21.37 41.76,131.22 v1(41.4,131.57) 41.06,131.57 40.76,131.27 J21.33 ; U10.3 21.07,33.34 ; R17.2 v1(50.16,26.29) ; J22.30 v1(8.99,103.41) ; U18.3 43.04,47.95 ; U7.4 23.76,22.98 ; U13.3 22.34,47.95 ; U14.3 14.21,33.34 ; U6.4 46.47,29.71 ; C35.1 v1(50.16,27.3) ; 61.09,69.09 60.33,69.09 v1(60.2,69.22) ; U11.3 27.93,33.34 ; U9.4 66.16,67.17 ; U8.4 16.88,51.17 ; C84.1 v1(10.92,53.09) ; U2.3 65.26,33.34 ; J21.18 v1(36.75,135.25) ; J22.18 v1(8.76,97.41)
  TOP w0.381: v1(38.86,92.33) v1(39.5,92.96) v1(40.13,93.6) 40.49,93.95 40.49,96.62 43.69,99.82 v1(48.39,99.82) 53.47,104.9 53.47,115.19 R170.1 C308.1 v1(59.69,119.38) ; C286.1 v1(64.9,134.75) ; v1(14.5,126.75) 14.99,127.23 TVS4.2 ; U16.8 34.58,31.28 ; C283.1 v1(62.87,131.7) ; C243.2 52.2,78.74 ; R72.2 C138.2 v1(40.26,53.47) ; R78.2 v1(33.4,35.56) ; U27.2 71.12,58.8 v1(70.99,58.67) ; C158.2 v1(42.04,42.8) ; TP42.1 21.21,16.51 ; 60.83,27.3 v1(61.72,27.3) ; C126.2 v1(22.48,45.59) ; C271.2 v1(18.67,129.03) ; J18.2 v1(74.4,127.23) ; v1(67.31,85.34) 66.95,84.99 U41.6 ; v1(52.83,109.47) C291.2 C292.1 ; TP26.1 v1(67.94,7.87) ; 60.83,25.15 61.47,25.15 v1(61.72,24.89) ; v1(14.22,31.11) 14.35,30.99 C132.2 ; v1(57.15,132.72) C296.2 ; C280.1 v1(67.82,119.51) ; U40.1 v1(63.37,83.06) ; Q2.2 v1(72.77,49.02) ; C23.2 v1(68.71,46.99) ; v1(38.73,43.18) C137.2 ; v1(57.53,74.17) C88.2 C95.2 C97.2 ; C40.2 v1(58.93,29.34) ; v1(42.42,117.6) C254.2 C255.1 ; C103.2 v1(20.07,28.45) ; C61.1 v1(40.39,25.27) ; C288.2 v1(61.23,114.43) 59.56,114.43 57.02,111.89 v1(57.02,109.22) 57.02,103 v1(56.01,101.98) v1(49.78,95.76) 49.78,92.84 v1(46.74,89.79) 45.09,88.14 v1(42.04,88.14) ; Q4.2 v1(54.29,125.48) ; C284.1 v1(57.15,131.7) ; C295.2 v1(62.87,132.72) ; U30.7 59.36,127.02 ; U37.4 v1(37.34,106.68) ; C272.2 v1(19.18,130.43) ; v1(26.92,37.72) 26.8,37.59 R55.2 ; TP25.1 57.4,62.61 ; 60.83,30.35 v1(61.72,30.35) ; C83.2 v1(13.97,53.98) ; C244.2 v1(55.5,77.09) ; R87.2 v1(41.91,52.2) ; C97.2 v1(57.53,71.5) ; C97.2 C94.2 ; K1.1 v1(76.96,51.91) ; U38.1 v1(63.37,87.5) ; R164.2 v1(71.5,136.91) ; C258.2 C259.1 v1(52.83,115.95) ; C72.1 21.21,17.91 ; TP43.1 v1(59.05,83.82) ; R65.2 v1(21.21,52.32) ; TP23.1 16.26,107.95 v1(15.88,108.33) ; R52.1 19.94,37.47 v1(20.45,37.97) ; 72.52,34.29 v1(71.75,34.29) ; v1(33.27,25.91) C145.2 C146.2 ; 36.77,10.29 v1(36.77,9.46) ; R163.2 v1(68.96,53.21) ; 72.52,37.44 v1(71.75,37.44) ; R69.2 v1(12.19,36.83) ; R59.2 v1(28.57,52.2) ; C278.1 v1(62.87,130.3) ; C242.2 52.2,83.69 ; TP41.1 v1(28.83,19.94) ; C273.1 v1(72.8,53.37) ; U1.2 v1(35.81,16.89) ; R6.2 v1(64.01,37.85) ; 60.83,31.37 v1(61.72,31.37) ; C41.2 v1(58.93,22.99) ; C248.2 v1(7.49,50.93) ; R267.2 v1(52.07,130.24) ; C59.2 v1(43.56,32.51) ; U33.3 v1(62.23,112.01) ; TVS5.2 v1(19.05,127.76) ; TP34.1 49.78,31.37 ; C246.2 52.83,75.18 v1(55.12,75.18) 55.5,74.8 v1(55.5,71.25) 55.12,70.87 52.96,70.87 52.32,71.5 C245.2 v1(51.44,71.5) ; TP39.1 57.15,53.59 ; TVS7.2 v1(66.17,106.43) ; C282.2 v1(68.83,116.71) ; U17.3 58.69,66.41 ; LED2.2 v1(7.49,21.72) ; C109.2 v1(26.8,28.32) ; U39.1 v1(63.37,91.95) ; R193.2 v1(66.55,107.7) ; TP38.1 v1(52.58,63.5)
  BOTTOM w0.254: C235.2 38.35,83.31 v3(38.73,82.93) ; C299.2 33.25,77.47 v3(33.19,77.41) ; C167.2 30.94,83.26 v3(31.24,83.26) ; v3(29.94,81.31) 29.79,81.15 C170.2 ; C241.2 33.15,78.11 v3(33.19,78.06) ; C191.2 26.29,77.47 v3(25.91,77.09) 26.29,76.71 C251.2 ; C224.2 31.24,80.01 v3(31.24,80.01) ; C233.2 28.57,73.53 v2(28.7,73.41) 29.21,73.41 C219.2 ; v3(29.94,80.01) 30.2,79.76 C165.2 ; v3(33.84,82.61) 33.78,82.55 C187.2 ; v3(27.99,79.36) 27.95,79.36 27.43,79.88 C171.2 26.62,80.09 C166.2 C172.2 ; v3(38.11,81.66) 37.86,81.41 C208.2 C210.2 ; C198.2 37.92,80.39 v3(37.97,80.44) ; v3(30.59,77.41) 30.78,77.6 31.11,77.6 ; C306.2 C225.2 C222.2 ; C185.2 31.3,82.55 v3(31.24,82.61) ; C232.2 C223.2
  BOTTOM w0.305: v3(29.94,74.81) 30.17,74.81 30.48,75.12 C234.2 ; R140.1 v1(38.73,101.73) ; C214.2 v2(31.24,72.14) 30.99,72.39 C227.2 C228.2 ; v3(37.72,85.6) C196.2 C194.2 ; R139.1 v1(41.02,101.73)
  BOTTOM w0.381: TVS11.2 v1(60.33,7.87) ; C195.2 v1(42.04,86.23) ; U31.7 60.02,127.02 ; R104.2 v1(77.47,60.83) ; C189.2 33.53,86.74 ; v1(67.31,70.61) 67.31,70.87 TVS6.2 ; v1(57.4,63.75) 57.53,63.88 R82.2 ; v1(70.61,72.52) 70.36,72.77 U29.1 ; C236.2 41.78,83.19 v1(41.91,83.31) ; v1(51.94,47.37) 52.58,48.01 C50.2 ; C207.2 41.78,80.39 v1(41.91,80.52) ; C152.2 57.15,67.06 v1(56.39,67.06) ; TVS3.1 v1(73.66,54.36) ; U34.1 v1(68.69,101.36) ; U23.6 v1(14.5,126.75) ; C183.2 C188.2 33.53,88.52 ; C238.1 v1(74.3,47.75) ; C297.2 v1(62.87,132.72) ; R171.1 v1(60.96,119.25) ; C240.2 v1(33.66,71.37) ; R93.2 v1(27.18,71.37) ; U26.1 v1(12.57,123.57) ; U25.1 20.19,123.32 v1(19.94,123.57) ; R103.2 v1(74.93,60.83) ; v1(56.39,66.04) 56.01,65.66 55.5,65.66 ; TVS15.2 67.94,84.45 ; R208.2 v1(15.88,111.89) ; v1(74.3,45.85) 74.3,46.23 TVS1.2 ; v1(41.15,110.49) C303.2 C304.2 ; C193.2 v1(41.91,84.71) ; C209.2 v1(41.91,81.92) R138.1 ; R1.2 v1(76.58,13.21) ; TVS13.2 v1(53.98,7.87) ; C298.2 v1(57.15,132.72) ; TVS10.2 v1(62.87,7.87) ; TVS2.1 v1(76.2,54.23) ; U36.3 11.83,109.84 ; C184.2 33.53,87.63 ; C308.1 v1(59.69,119.38) ; C290.1 v1(59.18,104.78) ; R98.2 v1(36.7,71.37) ; TVS9.2 v1(65.41,7.87) ; TVS12.2 v1(56.52,7.87) ; TVS8.2 v1(67.94,7.87) ; C197.2 41.81,78.87 v1(41.91,78.97) ; U24.1 v1(16.38,123.57) ; C289.1 v1(61.98,103.12)
  vias: v1(3.94,87.12) v1(3.94,85.85) v1(3.94,84.58) v1(5.08,103.63) v1(5.21,84.58) v1(6.35,106.17) v1(6.35,104.9) v1(6.35,103.63) v1(6.48,84.58) v1(6.58,98.18) v1(6.58,95.14) v1(8.26,63.63) v1(8.26,62.61) v1(8.26,61.59) v1(8.76,137.03) v1(8.76,135.64) v1(8.76,134.11) v1(9.02,124.46) v1(9.27,63.63) v1(9.27,62.61) v1(10.03,137.03) v1(10.03,134.11) v1(10.03,124.46) v1(10.29,63.63) v1(10.29,62.61) v1(10.79,113.92) v1(10.79,43.43) v1(10.79,42.42) v1(11.05,96.68) v1(11.05,93.89) v1(11.3,25.27) v1(11.43,111.76) v1(11.43,110.49) v1(11.43,109.22) v1(12.06,113.92) v1(12.19,99.69) v1(12.32,43.43) v1(12.32,42.42) v1(12.57,25.27) v1(13.97,55.12) v1(14.61,89.36) v1(14.61,87.08) v1(14.61,84.79) v1(14.61,82.51) v1(14.61,80.22) v1(14.61,77.93) v1(14.86,33.02) v1(16.13,51.31) v1(17.4,35.05) v1(17.4,34.04) v1(17.4,33.02) v1(17.4,32) v1(17.4,30.99) v1(18.16,56.39) v1(18.16,55.12) v1(18.16,53.85) v1(18.16,52.58) v1(18.16,51.31) v1(18.16,50.04) v1(18.16,48.77) v1(18.41,29.84) v1(18.54,25.27) v1(18.54,24) v1(19.43,61.34) v1(19.43,60.07) v1(19.43,58.8) v1(19.43,57.66) v1(19.43,56.39) v1(19.43,55.12) v1(19.43,53.85) v1(19.43,52.58) v1(19.43,51.31) v1(19.43,50.04) v1(19.43,48.77) v1(19.43,47.5) v1(19.43,46.23) v1(19.43,44.96) v1(19.81,25.27) v1(19.81,24) v1(20.45,40.64) v1(20.45,39.62) v1(20.45,33.02) v1(20.7,58.8) v1(20.7,57.66) v1(20.7,53.85) v1(20.95,19.56) v1(20.95,18.54) v1(20.95,17.14) v1(20.95,16.13) v1(21.08,25.27) v1(21.08,24) v1(21.46,40.64) v1(21.46,39.62) v1(21.72,33.02) v1(21.97,58.8) v1(21.97,57.66) v1(21.97,55.12) v1(21.97,53.85) v1(22.35,25.27) v1(22.35,24) v1(22.99,47.62) v1(22.99,33.02) v1(23.5,137.29) v1(23.5,136.02) v1(23.62,25.27) v1(23.62,24) v1(23.62,22.23) v1(23.62,20.95) v1(24.26,35.05) v1(24.26,34.04) v1(24.26,33.02) v1(24.26,30.99) v1(24.51,137.29) v1(24.51,136.02) v1(24.89,25.27) v1(24.89,24) v1(25.02,124.33) v1(25.02,123.44) v1(25.02,122.56) v1(25.53,137.29) v1(25.53,49.66) v1(25.53,48.64) v1(25.53,47.62) v1(25.53,46.61) v1(25.53,45.59) v1(25.53,43.69) v1(25.65,33.02) v1(26.16,25.27) v1(26.16,24) v1(26.92,40.64) v1(26.92,39.62) v1(26.92,33.02) v1(27.3,67.31) v1(27.43,25.27) v1(28.07,63.12) v1(28.07,62.1) v1(28.19,40.64) v1(28.19,39.62) v1(28.45,67.31) v1(28.45,66.04) v1(28.57,33.02) v1(28.7,25.27) v1(29.72,67.31) v1(29.72,66.04) v1(29.72,63.12) v1(29.72,62.1) v1(29.97,25.27) v1(30.48,47.62) v1(30.73,63.12) v1(30.73,62.1) v1(30.99,67.31) v1(31.11,34.54) v1(31.11,33.02) v1(31.11,32) v1(31.11,30.99) v1(31.11,29.08) v1(31.75,63.12) v1(31.75,62.1) v1(32.51,67.18) v1(32.77,63.12) v1(32.77,62.1) v1(32.89,49.66) v1(32.89,48.64) v1(32.89,47.62) v1(32.89,46.61) v1(32.89,45.59) v1(32.89,43.31) v1(33.4,40.64) v1(33.91,21.84) v1(33.91,20.83) v1(33.91,19.81) v1(33.91,9.91) v1(34.67,63.12) v1(34.67,62.1) v1(34.67,40.64) v1(34.8,50.42) v1(34.8,49.15) v1(34.8,47.88) v1(34.8,46.61) v1(34.8,45.34) v1(35.18,21.84) v1(35.18,20.83) v1(35.81,9.91) v1(37.34,67.06) v1(37.47,58.67) v1(38.27,32.38) v1(38.27,31.11) v1(38.27,29.84) v1(38.27,28.57) v1(38.35,67.06) v1(38.35,66.04) v1(39.24,58.67) v1(40.89,58.67) v1(40.89,57.53) v1(42.42,58.67) v1(42.42,57.53) v1(43.56,33.66) v1(43.69,47.62) v1(44.5,29.84) v1(45.72,29.84) v1(45.72,12.57) v1(45.72,11.3) v1(45.72,10.03) v1(45.72,8.76) v1(45.72,7.49) v1(46.23,49.66) v1(46.23,48.64) v1(46.23,47.62) v1(46.23,46.1) v1(46.23,43.43) v1(46.99,7.49) v1(47.5,53.72) v1(47.5,52.45) v1(47.5,51.18) v1(47.5,49.66) v1(47.5,48.64) v1(47.5,47.62) v1(47.5,46.1) v1(47.5,44.83) v1(47.5,43.56) v1(47.75,35.81) v1(47.75,34.8) v1(47.75,33.66) v1(47.75,32.38) v1(47.75,31.11) v1(47.75,29.84) v1(47.75,28.57) v1(47.75,27.3) v1(47.75,26.04) v1(48.26,7.49) v1(48.9,63.75) v1(48.9,62.61) v1(48.9,47.62) v1(48.9,46.1) v1(48.9,44.83) v1(48.9,43.56) v1(49.02,39.5) v1(49,38.35) v1(49,37.08) v1(49.02,35.81) v1(49,34.8) v1(49,33.66) v1(49,32.38) v1(49,31.11) v1(49,29.84) v1(49,28.57) v1(49,27.3) v1(49,26.04) v1(49,24.77) v1(49.53,22.35) v1(49.53,21.34) v1(49.53,12.57) v1(49.53,11.3) v1(49.53,10.03) v1(49.53,8.76) v1(49.53,7.49) v1(50.55,47.62) v1(50.55,46.1) v1(50.55,44.83) v1(50.55,43.56) v1(50.55,22.35) v1(50.55,21.34) v1(50.8,12.57) v1(50.8,11.3) v1(50.8,10.03) v1(50.8,8.76) v1(50.8,7.49) v1(50.93,40.64) v1(51.05,86.61) v1(51.18,78.74) v1(51.18,77.34) v1(51.82,10.03) v1(51.82,8.76) v1(51.82,7.49) v1(51.94,83.82) v1(51.94,40.64) v1(52.07,12.57) v1(52.07,11.3) v1(52.96,40.64) v1(53.09,78.74) v1(53.34,12.57) v1(53.34,11.3) v1(53.59,83.82) v1(53.72,88.01) v1(53.72,21.46) v1(54.23,40.64) v1(54.23,39.62) v1(54.48,63.5) v1(54.61,12.57) v1(54.99,90.3) v1(54.99,89.28) v1(54.99,88) v1(54.99,21.46) v1(55.12,78.74) v1(55.24,83.82) v1(55.5,40.64) v1(55.5,39.62) v1(55.63,62.48) v1(55.63,61.47) v1(55.88,118.87) v1(55.88,27.3) v1(55.88,12.57) v1(56.9,83.82) v1(56.9,81.41) v1(56.9,79.88) v1(56.9,62.48) v1(56.9,61.47) v1(57.02,123.57) v1(57.15,12.57) v1(57.4,115.57) v1(57.53,56.52) v1(57.53,54.74) v1(57.91,126.75) v1(58.04,66.67) v1(58.04,52.58) v1(58.04,51.44) v1(58.04,50.16) v1(58.04,48.9) v1(58.04,47.62) v1(58.04,46.35) v1(58.04,45.09) v1(58.04,43.81) v1(58.04,42.55) v1(59.21,52.58) v1(59.21,51.44) v1(59.21,50.16) v1(59.21,48.9) v1(59.21,46.35) v1(59.21,45.09) v1(59.21,43.81) v1(59.21,42.55) v1(59.31,66.67) v1(59.44,32.26) v1(59.69,126.11) v1(59.69,12.57) v1(60.45,32.26) v1(60.58,46.35) v1(60.58,45.09) v1(60.58,43.81) v1(60.58,42.55) v1(60.96,115.44) v1(60.96,108.58) v1(60.96,107.31) v1(60.96,12.57) v1(61.47,33.27) v1(61.47,32.26) v1(61.72,46.35) v1(61.72,45.09) v1(61.72,43.81) v1(61.72,42.55) v1(61.85,125.48) v1(61.98,12.57) v1(62.23,108.58) v1(62.23,107.31) v1(63.5,108.58) v1(63.5,107.31) v1(63.5,80.26) v1(63.75,115.44) v1(64.14,67.31) v1(64.64,80.26) v1(64.77,95.38) v1(64.77,94.23) v1(64.77,93.09) v1(65.15,40.51) v1(65.15,39.37) v1(65.41,67.31) v1(65.91,33.02) v1(66.04,93.09) v1(66.13,105.16) v1(66.13,102.11) v1(66.17,40.51) v1(66.17,39.37) v1(66.55,62.36) v1(66.55,61.34) v1(66.67,129.29) v1(67.18,33.02) v1(67.31,95.38) v1(67.31,94.23) v1(67.31,93.09) v1(67.31,69.6) v1(67.31,68.58) v1(67.31,67.31) v1(67.31,66.04) v1(67.69,125.6) v1(67.69,61.34) v1(68.33,122.81) v1(68.33,69.6) v1(68.33,68.58) v1(68.33,67.31) v1(68.33,66.04) v1(68.33,64.9) v1(68.33,63.37) v1(68.45,78.36) v1(68.45,75.95) v1(68.45,35.05) v1(68.45,34.04) v1(68.45,33.02) v1(68.45,32) v1(68.45,30.99) v1(68.58,84.71) v1(69.47,62.23) v1(69.47,60.96) v1(69.6,138.94) v1(69.6,137.79) v1(69.6,77.6) v1(69.6,36.07) v1(69.6,35.05) v1(69.6,34.04) v1(69.6,33.02) v1(69.6,32) v1(69.6,30.99) v1(69.6,29.97) v1(69.85,84.71) v1(70.23,130.94) v1(70.48,60.96) v1(70.61,75.31) v1(71.63,19.18) v1(71.63,17.91) v1(72.64,8.51) v1(73.91,8.51) v1(74.42,97.28) v1(74.42,95) v1(74.93,81.41) v1(75.69,97.28) v1(75.69,95) v1(76.2,81.41) v1(76.96,97.28) v1(76.96,95) v1(77.47,81.41) v1(77.47,80.14) v2(19.43,73.66) v2(19.43,72.64) v2(19.43,71.63) v2(19.56,79.76) v2(19.56,78.49) v2(19.56,77.22) v2(20.19,73.66) v2(20.19,72.64) v2(20.19,71.63) v2(20.45,79.76) v2(20.45,78.49) v2(20.45,77.22) v2(34.61,30.48) v2(35.56,31.05) v2(35.56,29.91) v2(36.51,47.62) v2(36.51,30.48) v2(37.47,48.2) v2(37.47,47.05) v2(38.42,47.62) v2(40.89,71.75) v2(41.78,75.95) v2(41.78,74.55) v2(41.78,71.75) v2(42.67,75.95) v2(42.67,74.55) v2(42.67,71.75) v2(43.56,75.95) v2(43.56,74.55) v2(43.56,71.75) v3(22.48,84.2) v3(22.99,83.57) v3(24,84.2) v3(24.51,83.69) v3(25.02,88.65) v3(25.02,87.76) v3(26.16,88.65) v3(26.16,87.76) v3(27.3,88.65) v3(27.3,87.76) v3(28.45,88.65) v3(28.45,87.76) v3(29.08,86.87) v3(29.72,88.65) v3(29.72,87.76) v3(32.64,87.9) v3(33.02,88.39) v3(36.96,74.55) v3(37.08,75.88) v3(37.85,78.61) v3(37.85,75.88) v3(37.85,74.55)
VBUS_CHARGE: length 10.8
  TOP w0.381: J2.1 38.86,11.43 37.97,12.32 37.97,19.3 37.47,19.81 LED1.1
  vias: v1(33.91,13.46) v1(33.91,12.45) v1(33.91,11.43) v1(35.43,12.45)
VBUS_IN: length 114.2
  TOP w0.381: 66.54,115.08 65.77,115.08 64.77,116.08 63.5,116.08 62.1,114.68 62.1,113.03 61.72,112.65 C288.1 U33.4
  BOTTOM w0.381: v1(62.23,19.43) 62.23,21.08 70.23,29.08 70.23,36.83 78.74,45.34 78.74,105.28 71.12,112.9 v1(71.12,113.54)
  vias: v1(50.8,19.43) v1(50.8,18.16) v1(52.07,19.43) v1(52.07,18.16) v1(53.34,19.43) v1(53.34,18.16) v1(54.61,19.43) v1(54.61,18.16) v1(55.88,19.43) v1(55.88,18.16) v1(57.15,19.43) v1(57.15,18.16) v1(59.69,19.43) v1(59.69,18.16) v1(60.96,19.43) v1(60.96,18.16) v1(62.23,18.16)
VDD0V8_CPU: length 4.1
  TOP w0.254: U19.G9 v3(32.54,79.36) ; U19.F9 v3(33.19,79.36) U19.E10 v3(33.19,78.71)
  TOP w0.381: TP4.1 56.13,57.02
  BOTTOM w0.254: C299.1 33.68,78.71 v3(33.19,78.71) ; v3(33.19,79.36) 33.05,79.5 C179.1
  vias: v1(40.39,36.2) v1(40.39,35.18) v1(40.39,34.29) v1(40.39,33.4) v1(40.39,32.51) v1(48.9,67.31) v1(48.9,66.33) v1(54.48,58.29) v1(54.48,57.28) v1(55.5,58.29) v1(55.5,57.28) v1(56.52,58.29) v1(56.52,57.28) v2(37.97,71.75) v2(38.86,71.75) v2(39.75,71.75) v3(38.86,75.88) v3(38.86,74.55)
VDD0V8_DDR_CORE: length 2.5
  TOP w0.254: U19.H10 v3(31.24,78.71) U19.J10 ; U19.K10 v3(30.59,78.71) ; U19.L10 v3(29.94,78.71)
  BOTTOM w0.305: C214.1 v2(30.23,72.14)
  vias: v1(21.59,63.12) v1(21.59,62.1) v1(22.61,63.12) v1(22.61,62.1) v1(23.62,63.12) v1(23.62,62.1) v2(27.3,70.48) v2(28.45,70.48)
VDD0V8_KPU: length 7.5
  TOP w0.254: U19.G5 v3(32.54,82.61) U19.F5 ; U19.F7 v3(32.54,81.31) U19.G7 ; U19.G6 v3(32.54,81.96) U19.F6
  BOTTOM w0.254: v3(32.54,81.96) 32.97,81.53 C187.1 ; v3(32.54,81.31) 32.32,81.53 C185.1
  BOTTOM w0.305: C183.1 35.81,89.41 ; C189.1 C184.1 35.94,87.63 ; C188.1 v2(36.07,88.52)
  vias: v1(48.26,89.41) v1(49.28,90.42) v1(49.28,88.52) v1(60.45,35.56) v1(61.47,36.58) v1(61.47,35.56) v1(61.47,34.54) v1(62.48,36.58) v1(62.48,35.56) v1(62.48,34.54) v1(65.02,56.77) v1(66.04,57.91) v1(66.04,56.77) v1(67.18,57.91) v1(67.18,56.77) v1(68.2,57.91) v1(68.2,56.77) v2(36.07,89.53) v2(36.83,91.06) v2(36.83,90.3) v2(36.83,89.53)
VDD1V1_DDR: length 9.6
  TOP w0.254: v3(31.89,78.71) U19.G11 32.36,78.24 32.72,78.24 U19.F11 ; U19.F15 v3(33.19,75.46) ; U19.K11 v3(29.94,78.06) U19.L11 ; U19.J11 v3(30.59,78.06) ; U19.M15 v3(29.29,75.46)
  BOTTOM w0.254: v3(31.89,78.71) 31.88,78.73 C224.1 ; v3(33.19,75.46) 33.98,74.68 C225.1 C222.1 ; C232.1 C223.1 29.76,78.09 30.56,78.09 v3(30.59,78.06)
  BOTTOM w0.305: R94.2 29.34,71.12 v2(29.34,70.48) ; C233.1 29.14,75.31 v3(29.29,75.46)
  vias: v1(33.4,37.34) v1(33.4,36.45) v1(34.67,37.34) v1(34.67,36.45) v1(36.07,37.34) v1(37.21,62.99) v1(37.21,61.98) v1(38.23,62.99) v1(38.23,61.98) v1(39.24,62.99) v1(39.24,61.98) v2(30.23,70.48) v2(31.11,70.48)
VDD1V1_DDR_DRAM: length 1.9
  TOP w0.254: v3(29.29,74.55) 29.29,74.81 U19.L16
  TOP w0.305: U19.F16 32.87,74.7
  BOTTOM w0.305: C306.1 v3(33.78,73.91)
VDD1V8_DDR_VDD1: length 7
  TOP w0.254: v3(31.24,76.11) U19.H14
  BOTTOM w0.381: 32,69.85 C227.1 C228.1 32,74.55 31.24,75.31 v3(31.24,76.11)
  vias: v1(24.89,40.77) v1(24.89,39.75) v1(24.89,38.73) v1(30.35,58.8) v1(30.99,58.17) v1(31.62,58.8)
VDD_0V8: length 13.1
  TOP w0.254: U19.J8 v3(31.24,80.66) U19.H8 ; U19.M8 v3(29.29,80.01) ; v3(33.84,80.66) U19.E7 U19.E6 ; U19.L6 v3(29.94,81.96) U19.K6 ; U19.H6 v3(31.24,81.96) U19.J6 ; U19.L8 v3(29.94,80.66) U19.K8 ; v3(33.19,80.01) U19.E9 ; U19.M10 v3(29.29,79.36)
  BOTTOM w0.254: v3(27.34,79.36) 26.98,78.99 C166.1 C172.1 ; v3(33.19,80.01) 33.7,80.52 C173.1 ; C170.1 29.29,80.09 C171.1 ; v3(31.24,80.66) 31.13,80.77 C165.1 30.05,80.77 v3(29.94,80.66) ; v3(29.29,80.01) v3(29.29,79.36) ; v3(29.94,81.96) 29.99,81.92 C167.1 31.2,81.92 v3(31.24,81.96)
  vias: v1(9.14,56.64) v1(9.14,55.37) v1(9.14,54.1) v1(10.76,56.64) v1(10.76,55.37) v1(10.76,54.1) v2(22.48,71.63) v2(23.5,73.66) v2(23.5,72.64) v2(23.5,71.63) v3(22.48,78.74) v3(22.86,77.6) v3(22.99,79.25) v3(22.99,76.33) v3(23.37,78.11) v3(23.5,76.83)
VDD_1V1: length 1
  BOTTOM w0.305: C300.1 R95.1
VDD_1V8: length 83.1
  TOP w0.203: v1(50.04,109.47) 49.98,109.42 U35.2 ; v1(49.91,116.84) 49.48,116.41 U21.2 ; U20.2 40.21,116.41 v1(40.64,116.84)
  TOP w0.254: U19.N11 v3(27.99,78.71) U19.N10 ; U19.D10 v3(34.49,79.36) ; U19.F4 v3(33.19,83.26) ; U19.H4 v3(31.89,83.26) ; U19.K4 v3(29.94,83.26) ; v3(33.21,80.65) U19.E8
  TOP w0.305: v1(57.53,86.11) R96.2 55.59,85.05 Y1.4 ; R136.1 v1(44.58,115.95) ; R132.1 v1(36.2,117.6) ; v1(49.91,116.84) C258.1 ; 61.09,63.75 v1(60.07,63.75) ; R63.2 23.11,43.81 ; C291.1 v1(50.04,109.47) ; R195.1 v1(44.83,109.73) ; C254.1 v1(40.64,116.84)
  TOP w0.381: R122.1 v1(7.49,33.78) ; R73.2 36.96,43.43 ; R123.1 v1(8.38,34.92) ; R125.1 7.49,42.42 v1(7.75,42.67) ; R168.1 v1(71.25,116.71) ; J7.1 C248.1 ; v1(7.75,44.2) 7.75,44.83 R126.1 ; U37.8 v1(44.07,110.49) ; R124.1 v1(8.38,37.47)
  ART03 w0.305: v1(60.07,63.75) 57.15,66.67 57.15,67.56 v1(56.77,67.94)
  BOTTOM w0.203: C249.1 33.92,81.42 33.21,80.7 v3(33.21,80.65)
  BOTTOM w0.254: v3(33.19,83.26) 33.27,83.34 C247.1 C250.1 ; C251.1 27.81,77.22 27.81,77.6 C191.1 27.39,78.11 v3(27.99,78.71) ; C192.1 30.61,83.92 v3(29.94,83.26)
  BOTTOM w0.305: v1(56.77,67.94) 57.28,68.45 R80.2 ; C253.2 31.75,83.4 v3(31.89,83.26) ; v1(3.56,91.31) R185.1 R186.1 ; R222.1 v1(9.65,105.28) ; v1(8.76,106.37) Q3.1 ; 42.55,134.49 41.4,134.49 v2(41.4,135.25) ; R212.1 35.69,111.51 v1(35.43,111.76)
  BOTTOM w0.381: 76.83,53.21 77.47,53.85 R101.2 ; 76.83,53.21 77.85,52.2 77.85,45.47 75.31,42.93 v1(74.55,42.93) ; 76.83,53.21 75.69,53.21 74.93,53.98 R99.2 ; v1(44.07,110.49) 43.05,110.49 43.05,109.22 ; R183.1 R181.1 R182.1 ; R183.1 R184.1 ; R183.1 v1(42.55,123.7) ; v1(73.03,42.93) 73.66,43.56 73.66,48.01 74.55,48.9 R89.1
  vias: v1(23.37,45.59) v1(23.37,43.69) v1(35.94,26.04) v1(36.07,42.93) v1(36.32,27.18) v1(37.08,42.93) v1(39.87,95.73) v1(39.87,94.61) v1(58.09,78.36) v1(58.17,77.47) v1(58.93,77.47) v1(58.97,78.36) v1(59.83,78.36) v1(59.82,77.47) v1(67.69,80.01) v1(68.71,80.01) v1(69.72,80.01) v1(70.87,80.01) v1(70.87,78.61) v3(29.72,90.17) v3(29.72,89.53)
VDD_1V8_ADC: length 41.7
  TOP w0.254: U19.D5 v3(34.49,82.61)
  TOP w0.381: 61.09,71.5 v1(60.2,71.5) C97.1 ; TP12.1 49.66,77.85 v1(49.66,78.36)
  BOTTOM w0.254: 37.84,84.45 37.63,84.24 36.16,84.24 35.94,84.45 ; 35.94,84.45 C194.1 ; 35.94,84.45 35.38,83.9 35.38,83.5 v3(34.49,82.61)
  BOTTOM w0.381: v1(60.2,71.5) 59.56,72.14 53.72,72.14 49.66,76.2 v1(49.66,78.36) 49.66,84.08 49.16,84.58 47.37,84.58 46.74,83.95 39.88,83.95 39.62,84.2 C193.1 38.1,84.71 37.84,84.45
VDD_1V8_CODEC: length 42.2
  TOP w0.254: U19.D4 v3(34.49,83.26)
  TOP w0.381: TP11.1 v1(50.29,79.38) ; 61.09,72.77 v1(60.2,72.77) C95.1
  BOTTOM w0.305: C196.1 35.31,85.6 34.92,85.22 34.92,83.69 v3(34.49,83.26)
  BOTTOM w0.381: C196.1 35.94,85.98 36.2,86.23 C195.1 39.62,85.85 40.01,85.47 44.45,85.47 45.21,84.71 46.48,84.71 46.99,85.22 49.28,85.22 50.29,84.2 v1(50.29,79.38) 50.29,76.45 53.98,72.77 v1(60.2,72.77)
VDD_1V8_USB: length 40.1
  TOP w0.254: v3(35.14,81.96) U19.C6
  TOP w0.381: TP10.1 v1(50.29,71.5) ; C94.1 v1(60.2,70.1) 61.09,70.1
  BOTTOM w0.254: 37.48,82.8 36.2,82.8 35.94,82.55 C210.1 35.48,82.3 v3(35.14,81.96)
  BOTTOM w0.381: v1(60.2,70.1) 59.83,70.47 51.32,70.47 v1(50.29,71.5) 49.02,72.77 49.02,81.03 48.01,82.04 45.47,82.04 44.58,81.15 39.88,81.15 39.62,81.41 C209.1 38.73,81.92 37.85,82.8 37.48,82.8
VDD_3V3: length 99
  TOP w0.254: U19.C9 v3(35.14,79.36)
  TOP w0.305: R50.2 21.84,29.08 ; R204.2 v1(52.83,107.31) ; J22.5 9,90.91 ; R57.2 30.73,44.45 ; v1(17.53,14.48) 21.59,14.48 22.1,14.99 24.26,14.99 R37.1 ; R155.1 15.75,129.03 ; R84.2 43.81,43.69 ; R224.2 v1(43.31,114.94) ; J22.6 8.99,91.41 ; R53.2 28.7,29.08
  TOP w0.381: U41.4 66.87,87.19 v1(66.93,87.25) ; 69.85,45.85 v1(69.85,44.96) ; TP6.1 v1(29.84,18.54) ; R226.2 v1(52.83,114.94)
  ART03 w0.381: v1(16.64,18.29) 16.64,15.37 v1(17.53,14.48) ; v1(52.83,114.94) 52.2,114.3 52.2,107.95 v1(52.83,107.31)
  BOTTOM w0.254: 38.23,79.25 38.01,79.46 36.2,79.46 35.94,79.21 C206.1 35.64,78.87 v3(35.14,79.36)
  BOTTOM w0.305: R223.1 v1(11.81,105.41) ; U23.4 v1(16.7,126.75)
  BOTTOM w0.381: 38.23,79.25 38.73,78.74 38.73,77.09 39.12,76.71 C205.1 39.62,77.22 39.9,77.5 44.3,77.5 46.1,75.69 46.1,72.26 50.16,68.2 50.16,64.26 54.23,60.2 56.77,60.2 58.17,58.8 58.17,55.69 v1(60.52,53.34) ; R275.1 R277.1 ; R275.1 R273.1 ; R275.1 v1(63.37,89.66) ; v1(64.14,85.47) 63.88,85.22 R274.1 R278.1 R276.1 ; v1(59.31,106.68) R194.2 ; R279.1 v1(70.23,83.06)
  vias: v1(9.02,91.19) v1(9.02,90.17) v1(16.64,19.3) v1(17.65,19.3) v1(17.65,18.29) v1(18.23,126.75) v1(19.24,126.75) v1(22.1,30.99) v1(22.23,28.96) v1(29.34,30.99) v1(29.34,29.08) v1(30.86,45.85) v1(31.11,43.31) v1(31.88,45.85) v1(35.43,119.38) v1(35.43,118.11) v1(35.43,116.84) v1(43.94,45.59) v1(44.83,45.59) v1(49.78,130.81) v1(49.78,129.54) v1(50.93,130.81) v1(68.96,87.76) v1(75.56,76.45) v1(75.56,75.44) v1(75.56,74.42) v1(75.56,73.41) v2(59.44,113.41) v2(59.44,112.65) v2(60.2,113.41) v2(60.2,112.65)
VDD_3V3_K210: length 23.7
  ART03 w0.305: 10.16,1.91 10.16,4.45 7.87,6.73 7.87,19.68 8.76,20.57 v1(8.76,24.26)
VDD_3V3_USB: length 107
  TOP w0.254: U19.C7 v3(35.14,81.31)
  ART03 w0.381: v1(17.53,16) v1(17.53,17.14) 18.16,17.78 21.08,17.78 22.48,19.18 22.48,22.86 21.72,23.62 21.72,27.81 19.68,29.84 19.68,41.78 20.45,42.55 20.45,47.75 25.53,52.83 25.53,57.66 27.69,59.82 43.94,59.82 50.55,66.42 50.55,68.83 v1(51.31,69.6)
  BOTTOM w0.254: 38.23,80.9 36.2,80.9 35.94,81.15 C208.1 35.94,81.53 35.37,81.53 v3(35.14,81.31)
  BOTTOM w0.381: v1(51.31,69.6) 48.26,72.64 48.26,79.12 47.75,79.63 40.01,79.63 39.62,80.01 C207.1 39.12,80.9 38.23,80.9
